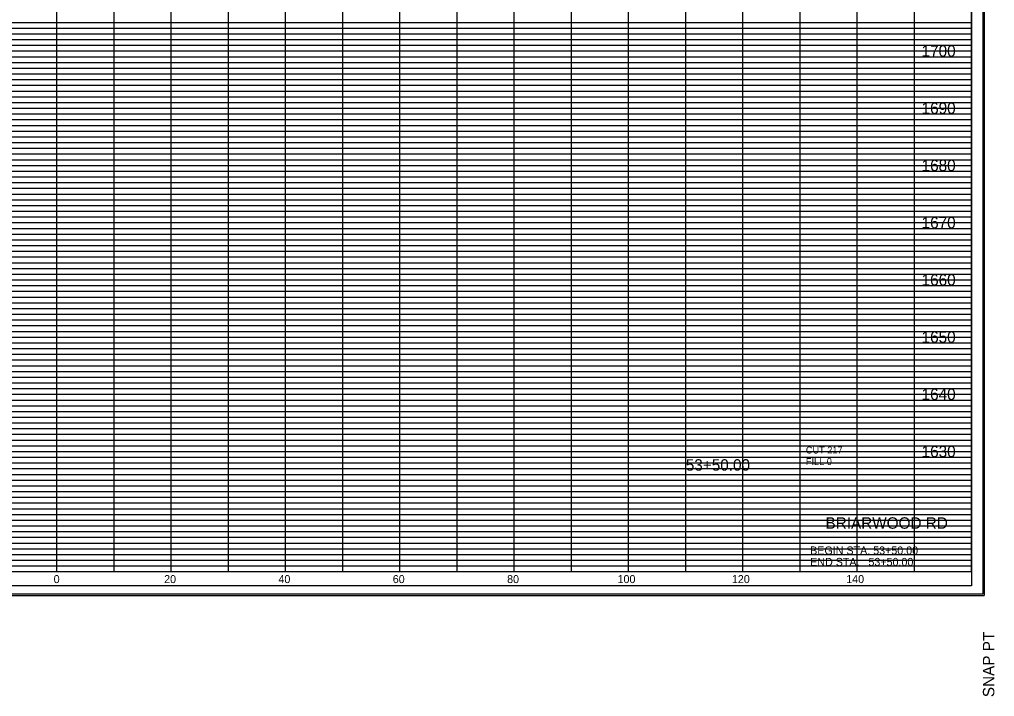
# Model space of a CAD drawing. Extents: x 980 to 2228, y 978 to 2394.
# Drawn here: x 1153.4 to 1324, y 1788.2 to 1906.5 of the extents above; entities that cross this region are included whole.
import ezdxf

# ---------------------------------------------------------------- set-up
doc = ezdxf.new("R2010")
doc.units = 0
for name, color, linetype in [('DESIGN - SHEET - Corner Text', 7, 'Continuous'), ('DESIGN - SHEET - Light Grid', 7, 'Continuous'), ('DESIGN - SHEET - Linework', 7, 'Continuous'), ('DESIGN - SHEET - Plot Shape', 7, 'Continuous'), ('DESIGN - TYPICAL - Finished Grade and Subgrade', 7, 'Continuous'), ('DESIGN - TYPICAL - Text', 7, 'Continuous')]:
    doc.layers.add(name, color=color, linetype=linetype)

# ---------------------------------------------------------------- blocks, each defined once
blk = doc.blocks.new('XSTSHT')
at = {"layer": 'DESIGN - SHEET - Light Grid'}
for p, q in [((8, 9.6), (16, 9.6)), ((16, 9.6), (24, 9.6)), ((24, 9.6), (32, 9.6)), ((8, 9.5), (16, 9.5)), ((8, 9.4), (16, 9.4)), ((16, 9.5), (24, 9.5)), ((16, 9.4), (24, 9.4)), ((24, 9.5), (32, 9.5)), ((24, 9.4), (32, 9.4)), ((8, 9.3), (16, 9.3)), ((16, 9.3), (24, 9.3)), ((24, 9.3), (32, 9.3)), ((8, 9.2), (16, 9.2)), ((8, 9.1), (16, 9.1)), ((16, 9.2), (24, 9.2)), ((16, 9.1), (24, 9.1)), ((24, 9.2), (32, 9.2)), ((24, 9.1), (32, 9.1)), ((8, 8.9), (16, 8.9)), ((16, 8.9), (24, 8.9)), ((24, 8.9), (32, 8.9)), ((8, 8.8), (16, 8.8)), ((8, 8.7), (16, 8.7)), ((16, 8.8), (24, 8.8)), ((16, 8.7), (24, 8.7)), ((24, 8.8), (32, 8.8)), ((24, 8.7), (32, 8.7)), ((8, 8.6), (16, 8.6)), ((16, 8.6), (24, 8.6)), ((24, 8.6), (32, 8.6)), ((8, 8.5), (16, 8.5)), ((8, 8.4), (16, 8.4)), ((16, 8.5), (24, 8.5)), ((16, 8.4), (24, 8.4)), ((24, 8.5), (32, 8.5)), ((24, 8.4), (32, 8.4)), ((8, 8.3), (16, 8.3)), ((8, 8.2), (16, 8.2)), ((16, 8.3), (24, 8.3)), ((16, 8.2), (24, 8.2)), ((24, 8.3), (32, 8.3)), ((24, 8.2), (32, 8.2)), ((8, 8.1), (16, 8.1)), ((16, 8.1), (24, 8.1)), ((24, 8.1), (32, 8.1)), ((8, 7.9), (16, 7.9)), ((16, 7.9), (24, 7.9)), ((24, 7.9), (32, 7.9)), ((8, 7.8), (16, 7.8)), ((8, 7.7), (16, 7.7)), ((16, 7.8), (24, 7.8)), ((16, 7.7), (24, 7.7)), ((24, 7.8), (32, 7.8)), ((24, 7.7), (32, 7.7)), ((8, 7.6), (16, 7.6)), ((16, 7.6), (24, 7.6)), ((24, 7.6), (32, 7.6)), ((8, 7.5), (16, 7.5)), ((8, 7.4), (16, 7.4)), ((16, 7.5), (24, 7.5)), ((16, 7.4), (24, 7.4)), ((24, 7.5), (32, 7.5)), ((24, 7.4), (32, 7.4)), ((8, 7.3), (16, 7.3)), ((8, 7.2), (16, 7.2)), ((16, 7.3), (24, 7.3)), ((16, 7.2), (24, 7.2)), ((24, 7.3), (32, 7.3)), ((24, 7.2), (32, 7.2)), ((8, 7.1), (16, 7.1)), ((16, 7.1), (24, 7.1)), ((24, 7.1), (32, 7.1)), ((8, 6.9), (16, 6.9)), ((16, 6.9), (24, 6.9)), ((24, 6.9), (32, 6.9)), ((8, 6.8), (16, 6.8)), ((8, 6.7), (16, 6.7)), ((16, 6.8), (24, 6.8)), ((16, 6.7), (24, 6.7)), ((24, 6.8), (32, 6.8)), ((24, 6.7), (32, 6.7)), ((8, 6.6), (16, 6.6)), ((8, 6.5), (16, 6.5)), ((16, 6.6), (24, 6.6)), ((16, 6.5), (24, 6.5)), ((24, 6.6), (32, 6.6)), ((24, 6.5), (32, 6.5)), ((8, 6.4), (16, 6.4)), ((16, 6.4), (24, 6.4)), ((24, 6.4), (32, 6.4)), ((8, 6.3), (16, 6.3)), ((8, 6.2), (16, 6.2)), ((16, 6.3), (24, 6.3)), ((16, 6.2), (24, 6.2)), ((24, 6.3), (32, 6.3)), ((24, 6.2), (32, 6.2)), ((8, 6.1), (16, 6.1)), ((16, 6.1), (24, 6.1)), ((24, 6.1), (32, 6.1)), ((8, 5.9), (16, 5.9)), ((8, 5.8), (16, 5.8)), ((16, 5.9), (24, 5.9)), ((16, 5.8), (24, 5.8)), ((24, 5.9), (32, 5.9)), ((24, 5.8), (32, 5.8)), ((8, 5.7), (16, 5.7)), ((16, 5.7), (24, 5.7)), ((24, 5.7), (32, 5.7)), ((8, 5.6), (16, 5.6)), ((8, 5.5), (16, 5.5)), ((16, 5.6), (24, 5.6)), ((16, 5.5), (24, 5.5)), ((24, 5.6), (32, 5.6)), ((24, 5.5), (32, 5.5)), ((8, 5.4), (16, 5.4)), ((8, 5.3), (16, 5.3)), ((16, 5.4), (24, 5.4)), ((16, 5.3), (24, 5.3)), ((24, 5.4), (32, 5.4)), ((24, 5.3), (32, 5.3)), ((8, 5.2), (16, 5.2)), ((16, 5.2), (24, 5.2)), ((24, 5.2), (32, 5.2)), ((8, 5.1), (16, 5.1)), ((16, 5.1), (24, 5.1)), ((24, 5.1), (32, 5.1)), ((8, 4.9), (16, 4.9)), ((8, 4.8), (16, 4.8)), ((16, 4.9), (24, 4.9)), ((16, 4.8), (24, 4.8)), ((24, 4.9), (32, 4.9)), ((24, 4.8), (32, 4.8)), ((8, 4.7), (16, 4.7)), ((16, 4.7), (24, 4.7)), ((24, 4.7), (32, 4.7)), ((8, 4.6), (16, 4.6)), ((8, 4.5), (16, 4.5)), ((16, 4.6), (24, 4.6)), ((16, 4.5), (24, 4.5)), ((24, 4.6), (32, 4.6)), ((24, 4.5), (32, 4.5)), ((8, 4.4), (16, 4.4)), ((8, 4.3), (16, 4.3)), ((16, 4.4), (24, 4.4)), ((16, 4.3), (24, 4.3)), ((24, 4.4), (32, 4.4)), ((24, 4.3), (32, 4.3)), ((8, 4.2), (16, 4.2)), ((8, 4.1), (16, 4.1)), ((16, 4.2), (24, 4.2)), ((16, 4.1), (24, 4.1)), ((24, 4.2), (32, 4.2)), ((24, 4.1), (32, 4.1)), ((8, 3.9), (16, 3.9)), ((8, 3.8), (16, 3.8)), ((16, 3.9), (24, 3.9)), ((16, 3.8), (24, 3.8)), ((24, 3.9), (32, 3.9)), ((24, 3.8), (32, 3.8)), ((8, 3.7), (16, 3.7)), ((8, 3.6), (16, 3.6)), ((16, 3.7), (24, 3.7)), ((16, 3.6), (24, 3.6)), ((24, 3.7), (32, 3.7)), ((24, 3.6), (32, 3.6)), ((8, 3.5), (16, 3.5)), ((16, 3.5), (24, 3.5)), ((24, 3.5), (32, 3.5)), ((8, 3.4), (16, 3.4)), ((8, 3.3), (16, 3.3)), ((16, 3.4), (24, 3.4)), ((16, 3.3), (24, 3.3)), ((24, 3.4), (32, 3.4)), ((24, 3.3), (32, 3.3)), ((8, 3.2), (16, 3.2)), ((8, 3.1), (16, 3.1)), ((16, 3.2), (24, 3.2)), ((16, 3.1), (24, 3.1)), ((24, 3.2), (32, 3.2)), ((24, 3.1), (32, 3.1)), ((8, 2.9), (16, 2.9)), ((16, 2.9), (24, 2.9)), ((24, 2.9), (32, 2.9)), ((8, 2.8), (16, 2.8)), ((16, 2.8), (24, 2.8)), ((24, 2.8), (32, 2.8)), ((8, 2.7), (16, 2.7)), ((8, 2.6), (16, 2.6)), ((16, 2.7), (24, 2.7)), ((16, 2.6), (24, 2.6)), ((24, 2.7), (32, 2.7)), ((24, 2.6), (32, 2.6)), ((8, 2.5), (16, 2.5)), ((8, 2.4), (16, 2.4)), ((16, 2.5), (24, 2.5)), ((16, 2.4), (24, 2.4)), ((24, 2.5), (32, 2.5)), ((24, 2.4), (32, 2.4)), ((8, 2.3), (16, 2.3)), ((16, 2.3), (24, 2.3)), ((24, 2.3), (32, 2.3)), ((8, 2.2), (16, 2.2)), ((8, 2.1), (16, 2.1)), ((16, 2.2), (24, 2.2)), ((16, 2.1), (24, 2.1)), ((24, 2.2), (32, 2.2)), ((24, 2.1), (32, 2.1)), ((8, 1.9), (16, 1.9)), ((16, 1.9), (24, 1.9)), ((24, 1.9), (32, 1.9)), ((8, 1.8), (16, 1.8)), ((16, 1.8), (24, 1.8)), ((24, 1.8), (32, 1.8)), ((8, 1.7), (16, 1.7)), ((8, 1.6), (16, 1.6)), ((16, 1.7), (24, 1.7)), ((16, 1.6), (24, 1.6)), ((24, 1.7), (32, 1.7)), ((24, 1.6), (32, 1.6)), ((8, 1.5), (16, 1.5)), ((8, 1.4), (16, 1.4)), ((16, 1.5), (24, 1.5)), ((16, 1.4), (24, 1.4)), ((24, 1.5), (32, 1.5)), ((24, 1.4), (32, 1.4)), ((8, 1.3), (16, 1.3)), ((8, 1.2), (16, 1.2)), ((16, 1.3), (24, 1.3)), ((16, 1.2), (24, 1.2)), ((24, 1.3), (32, 1.3)), ((24, 1.2), (32, 1.2)), ((8, 1.1), (16, 1.1)), ((16, 1.1), (24, 1.1)), ((24, 1.1), (32, 1.1)), ((8, 0.9), (16, 0.9)), ((16, 0.9), (24, 0.9)), ((24, 0.9), (32, 0.9)), ((8, 0.8), (16, 0.8)), ((8, 0.7), (16, 0.7)), ((16, 0.8), (24, 0.8)), ((16, 0.7), (24, 0.7)), ((24, 0.8), (32, 0.8)), ((24, 0.7), (32, 0.7)), ((8, 0.6), (16, 0.6)), ((16, 0.6), (24, 0.6)), ((24, 0.6), (32, 0.6)), ((8, 0.5), (16, 0.5)), ((8, 0.4), (16, 0.4)), ((16, 0.5), (24, 0.5)), ((16, 0.4), (24, 0.4)), ((24, 0.5), (32, 0.5)), ((24, 0.4), (32, 0.4)), ((8, 0.3), (16, 0.3)), ((8, 0.2), (16, 0.2)), ((16, 0.3), (24, 0.3)), ((16, 0.2), (24, 0.2)), ((24, 0.3), (32, 0.3)), ((24, 0.2), (32, 0.2)), ((8, 0.1), (16, 0.1)), ((16, 0.1), (24, 0.1)), ((24, 0.1), (32, 0.1))]:
    blk.add_line(p, q, dxfattribs=at)
at = {"layer": 'DESIGN - SHEET - Linework'}
for p, q in [((32.217, 21.414), (32.217, -0.414)), ((16, 0), (16, 21)), ((17, 0), (17, 21)), ((18, 0), (18, 21)), ((19, 0), (19, 21)), ((20, 0), (20, 21)), ((21, 0), (21, 21)), ((22, 0), (22, 21)), ((23, 0), (23, 21)), ((24, 0), (24, 21)), ((25, 0), (25, 21)), ((26, 0), (26, 21)), ((27, 0), (27, 21)), ((28, 0), (28, 20)), ((29, 0), (29, 20)), ((30, 0), (30, 20)), ((31, 0), (31, 20)), ((0, 9), (32, 9)), ((0, 8), (32, 8)), ((0, 7), (32, 7)), ((0, 6), (32, 6)), ((0, 5), (32, 5)), ((0, 4), (32, 4)), ((0, 3), (32, 3)), ((0, 2), (32, 2)), ((0, 1), (32, 1)), ((-1.823, -0.414), (32.217, -0.414))]:
    blk.add_line(p, q, dxfattribs=at)
blk.add_lwpolyline([(0, 21), (0, 0), (32, 0), (32, 21), (0, 21)], dxfattribs=at)
at = {"layer": 'DESIGN - SHEET - Plot Shape'}
for points in [[(-1.803, 21.394), (32.197, 21.394), (32.197, -0.394), (-1.803, -0.394)], [(-0.85, 21), (32, 21), (32, -0.25), (-0.85, -0.25)]]:
    blk.add_lwpolyline(points, close=True, dxfattribs=at)
at = {"layer": 'DESIGN - SHEET - Corner Text'}
blk.add_text('SNAP PT  ', height=0.2, rotation=90, dxfattribs=at).set_placement((32.397, -2.194))

msp = doc.modelspace()

# ---------------------------------------------------------------- linework, layer by layer
at = {"layer": 'DESIGN - SHEET - Plot Shape'}
msp.add_lwpolyline([(991.5, 2020), (1320, 2020), (1320, 1807.5), (991.5, 1807.5)], close=True, dxfattribs=at)

# ---------------------------------------------------------------- block references
at = {"layer": 'DESIGN - TYPICAL - Finished Grade and Subgrade', "xscale": 10, "yscale": 10}
msp.add_blockref('XSTSHT', (1000, 1810), dxfattribs=at)

# ---------------------------------------------------------------- texts
at = {"layer": 'DESIGN - SHEET - Corner Text'}
for s, height, p in [('1700', 2, (1311.25, 1900)), ('1690', 2, (1311.25, 1890)), ('1680', 2, (1311.25, 1880)), ('1670', 2, (1311.25, 1870)), ('1660', 2, (1311.25, 1860)), ('1650', 2, (1311.25, 1850)), ('1640', 2, (1311.25, 1840)), ('1630', 2, (1311.25, 1830)), ('BRIARWOOD RD', 2, (1294.44, 1817.5)), ('BEGIN STA. 53+50.00', 1.4, (1291.75, 1813)), ('END STA.   53+50.00', 1.4, (1291.75, 1811)), ('0', 1.4, (1159.42, 1808)), ('0', 1.4, (1159.42, 1808)), ('20', 1.4, (1178.74, 1808)), ('40', 1.4, (1198.74, 1808)), ('60', 1.4, (1218.74, 1808)), ('80', 1.4, (1238.74, 1808)), ('100', 1.4, (1258.06, 1808)), ('120', 1.4, (1278.06, 1808)), ('140', 1.4, (1298.06, 1808))]:
    msp.add_text(s, height=height, dxfattribs=at).set_placement(p)
at = {"layer": 'DESIGN - TYPICAL - Text'}
for s, height, p in [('CUT 217', 1.2, (1291, 1830.65)), ('53+50.00', 2, (1270, 1827.65)), ('FILL 0', 1.2, (1291, 1828.65))]:
    msp.add_text(s, height=height, dxfattribs=at).set_placement(p)

doc.saveas('drawing.dxf')
